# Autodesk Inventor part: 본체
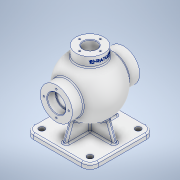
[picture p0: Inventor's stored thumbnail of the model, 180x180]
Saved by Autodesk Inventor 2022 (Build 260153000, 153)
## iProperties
Created: 2024-04
Part Number: 본체
Material: 알루미늄 6061
Document SubType Name: Modeling
Designer: user
Density: 2.7 g/cm^3
Appearance: 알루미늄 - 평지
Mass: 1526.73 g
Surface Area: 1173.98 cm^2
Volume: 565.456 cm^3
Author: user
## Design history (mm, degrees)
sketch "스케치1"
  geometry: L1 (64.8, 0)-(-10.8, 0) reference; L2 (0, -185.251)-(0, 154.667) reference; L3 (31, 65)-(31, 44.215); L4 (31, -44.215)-(31, -65); L5 (31, 65)-(0, 65); L6 (31, -65)-(0, -65); L7 (0, -65)-(0, 65); L8 (0, -136.691)-(0, 106.107); A1 r 54 centre (0, 0) between (31, -44.215) and (31, 44.215); 1 further point
  constraints: 12 end point, 4 point on line, 2 perpendicular, 2 point on circle, 2 vertical, 1 centre point, 1 coincident, 1 collinear, 1 symmetric about line
  dimensions: "d0" = 108 diameter of A1; "d2" = 31 distance between parallel lines of L4 L2; "d4" = 130 distance of L4.end L3.start
revolve "회전1" sketch "스케치1" stored, may be unused: angle "d5" = 360 deg
sketch "스케치2"
  geometry: C1 r 27 at (0, 0); 1 further point
  constraints: 1 centre point, 1 coincident
  dimensions: "d6" = 54 diameter of C1
extrude "돌출1" join sketch "스케치2" distance "d7" = 65; taper "d8" = 0 deg
node "작업 평면1"
sketch "스케치3"
  geometry: L1 (62.5, 62.5)-(-62.5, 62.5); L2 (-62.5, 62.5)-(-62.5, -62.5); L3 (-62.5, -62.5)-(62.5, -62.5); L4 (62.5, -62.5)-(62.5, 62.5); L5 (62.5, 62.5)-(-62.5, -62.5); L6 (-62.5, 62.5)-(62.5, -62.5); 1 further point
  constraints: 12 end point, 2 midpoint, 2 parallel, 1 horizontal, 1 perpendicular
  dimensions: "d10" = 125 distance of L3.end L1.start; "d11" = 125 distance of L2.end L3.end
extrude "돌출2" join sketch "스케치3" distance "d12" = 10; taper "d13" = 0 deg
sketch "스케치4"
  geometry: L1 (0, 23.202)-(0, -23.202); L2 (0, -23.202)-(-75, -50.5); L3 (-75, -62.5)-(-75, 62.5) reference; L4 (0, 23.202)-(-75, 50.5); L5 (-75, 50.5)-(-75, -50.5); L6 (-102, 0)-(17, 0) reference; L7 (0, -87.5)-(0, 87.5) reference; L8 (-85, -62.5)-(-75, -62.5) reference; 2 further points
  constraints: 8 end point, 2 symmetric about line, 1 collinear, 1 parallel, 1 point on line, 1 vertical
  dimensions: "d14" = 20 deg angle of L8 L2; "d15" = 12 distance of L3.start L2.end
extrude "돌출3" join sketch "스케치4" stored distance "d16" = 8; taper "d17" = 0 deg
sketch "스케치5"
  geometry: L1 (-23.202, 0)-(23.202, 0); L2 (23.202, 0)-(50.5, -75); L3 (62.5, -75)-(-62.5, -75) reference; L4 (-23.202, 0)-(-50.5, -75); L5 (-50.5, -75)-(50.5, -75); L6 (0, -102)-(0, 17) reference; L7 (62.5, -85)-(62.5, -75) reference; L8 (-62.5, -85)-(-62.5, -75) reference; L9 (-87.5, 0)-(87.5, 0) reference; 1 further point
  constraints: 8 end point, 2 point on line, 2 symmetric about line, 1 collinear, 1 horizontal, 1 parallel
  dimensions: "d20" = 20 deg angle of L8 L4; "d21" = 12 distance of L3.end L4.end
extrude "돌출4" join sketch "스케치5" stored distance "d22" = 8; taper "d23" = 0 deg
sketch "스케치6"
  geometry: L1 (-31, -65)-(31, -65) reference; L2 (0, -65)-(17.5, -65); L3 (17.5, -65)-(17.5, -49); L4 (17.5, -49)-(0, -49); L5 (0, -49)-(0, -65); L6 (0, -49)-(15, -49); L7 (15, -49)-(15, -41.364); L8 (15, -41.364)-(0, -41.364); L9 (0, -41.364)-(0, -49); L10 (0, -91)-(0, 91) reference; L11 (75.6, 0)-(-75.6, 0) reference; L12 (-31, 65)-(31, 65) reference; L13 (0, 65)-(17.5, 65); L14 (17.5, 65)-(17.5, 49); L15 (17.5, 49)-(0, 49); L16 (0, 49)-(0, 65); L17 (0, 49)-(15, 49); L18 (15, 49)-(15, 41.364); L19 (15, 41.364)-(0, 41.364); L20 (0, 41.364)-(0, 49); L21 (0, 41.364)-(0, -41.364); A1 r 54 centre (0, 0) between (31, -44.215) and (-31, -44.215) reference; A2 r 44 centre (0, 0) between (15, -41.364) and (15, 41.364); 6 further points
  constraints: 34 end point, 8 parallel, 4 horizontal, 4 perpendicular, 4 point on line, 2 midpoint, 2 point on circle, 1 centre point, 1 collinear
  dimensions: "d25" = 16 distance of L2.end L3.end; "d26" = 35 diameter of L3 L10; "d27" = 30 diameter of L7 L10; "d28" = 35 diameter of L14 L10; "d29" = 30 diameter of L18 L10; "d30" = 16 distance of L13.end L14.end; "d31" = 44 radius of A2
revolve "회전2" sketch "스케치6" stored, may be unused: angle "d32" = 360 deg
sketch "스케치7"
  geometry: C1 r 13 at (0, 0); 1 further point
  constraints: 1 centre point, 1 coincident
  dimensions: "d33" = 26 diameter of C1
extrude "돌출5" cut sketch "스케치7" stored distance "d34" = 8; taper "d35" = 0 deg
fillet "모깎기1" dims "d36" = 16
sketch "스케치8"
  geometry: L1 (-62.5, 46.5)-(-62.5, -46.5) reference; L2 (-46.5, -62.5)-(46.5, -62.5) reference; L3 (62.5, -46.5)-(62.5, 46.5) reference; L4 (46.5, 62.5)-(-46.5, 62.5) reference; L5 (-4, -4)-(-50.5, -4) reference; L6 (-50.5, -4)-(-50.5, 4) reference; L7 (-50.5, 4)-(-4, 4) reference; L8 (-4, 4)-(-4, 50.5) reference; L9 (-4, 50.5)-(4, 50.5) reference; L10 (4, 50.5)-(4, 4) reference; L11 (4, 4)-(50.5, 4) reference; L12 (50.5, 4)-(50.5, -4) reference; L13 (50.5, -4)-(4, -4) reference; L14 (4, -4)-(4, -50.5) reference; L15 (4, -50.5)-(-4, -50.5) reference; L16 (-4, -50.5)-(-4, -4) reference; A1 r 16 centre (-46.5, 46.5) between (-46.5, 62.5) and (-62.5, 46.5) reference; A2 r 16 centre (-46.5, -46.5) between (-62.5, -46.5) and (-46.5, -62.5) reference; A3 r 16 centre (46.5, -46.5) between (46.5, -62.5) and (62.5, -46.5) reference; A4 r 16 centre (46.5, 46.5) between (62.5, 46.5) and (46.5, 62.5) reference; 5 further points
  constraints: 4 coincident
hole "구멍1" sketch "스케치8" at (-46.5, 46.5), (46.5, 46.5), (46.5, -46.5), (-46.5, -46.5) diameter "d37" = 11; stored, may be unused: countersink angle "d41" = 90 deg, drill point angle "d43" = 118 deg; dims "d38" = 30, "d39" = 4, "d40" = 2, "d42" = 30
node "작업 평면2"
sketch "스케치9"
  geometry: L1 (65, -27)-(65, 27) reference; 2 further points
  constraints: 1 horizontal alignment, 1 other
  dimensions: "d45" = 9 distance from line of L1 point (56, 0)
feature "엠보싱1" sketch "스케치9" dims "d1" = 31, "d10" = 125, "d11" = 125, "d46" = 0.5, "d47" = 0
chamfer "모따기1" distance "d48" = 1; stored, may be unused: second distance "d49" = 2, angle "d50" = 45 deg
fillet "모깎기2" dims "d51" = 0.6
sketch "스케치10" dims "d52" = 48
  geometry: 3 further points
  constraints: 2 vertical alignment, 1 coincident, 2 other
hole "구멍2" sketch "스케치10" at (0, 24) diameter "d53" = 3.242; stored, may be unused: countersink angle "d57" = 90 deg, drill point angle "d59" = 118 deg; dims "d54" = 12, "d55" = 4, "d56" = 2, "d58" = 15
sketch "스케치11" dims "d63" = 40
  geometry: 3 further points
  constraints: 2 vertical alignment, 1 coincident, 2 other
hole "구멍3" sketch "스케치11" at (0, 20) diameter "d64" = 3.242; stored, may be unused: countersink angle "d68" = 90 deg, drill point angle "d70" = 118 deg; dims "d65" = 9, "d66" = 4, "d67" = 2, "d69" = 11
fillet "모깎기3" dims "d74" = 3
fillet "모깎기4" dims "d75" = 3
node "솔리드1"
pattern_circular "원형 패턴1" dims angle "d61" = 360 deg
mirror "미러1"
pattern_circular "원형 패턴2" dims angle "d72" = 360 deg
node "투영된 루프1"
feature "A9D066F2-1C7D-4E18-AEED-F7BC21143FA4" dims "d37" = 11, "d38" = 30, "d39" = 4, "d40" = 2, "d41" = 90 deg, "d42" = 30, "d43" = 118 deg
other parameters: "d9" = -85, "d44" = 54
